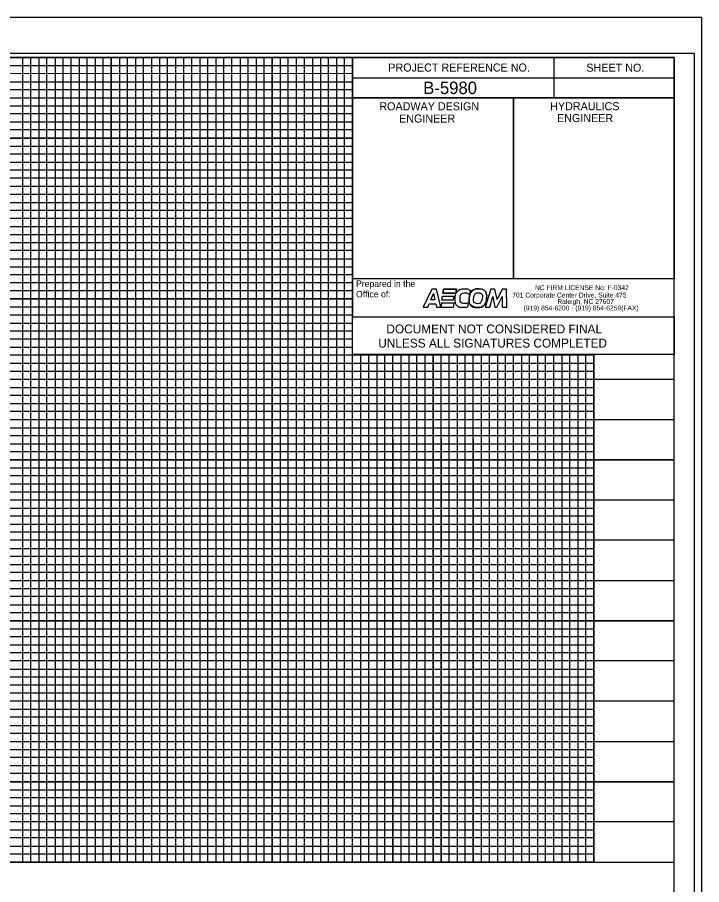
# Model space of a CAD drawing. Extents: x 2356353 to 2358037, y 848519 to 849619.
# Drawn here: x 2357612 to 2358037, y 849080 to 849619 of the extents above; entities that cross this region are included whole.
import ezdxf

# ---------------------------------------------------------------- set-up
doc = ezdxf.new("R2010")
doc.units = 0
for name, color, linetype in [('Default', 7, 'Continuous'), ('Old_Level_49', 7, 'Continuous'), ('Sheet Cutting Line CELL', 7, 'Continuous'), ('Sheet Data Field CELL', 7, 'Continuous'), ('Sheet DOT Grid CELL', 7, 'Continuous'), ('Sheet Layout Profile Border Port 1', 7, 'Continuous'), ('Sheet Plot Border Inside CELL', 7, 'Continuous'), ('Sheet Plot Border Outside CELL', 7, 'Continuous'), ('Sheet Profile CELL', 7, 'Continuous'), ('Sheet Profile Grid Major CELL', 7, 'Continuous'), ('Sheet Profile Grid Middle CELL', 7, 'Continuous'), ('Sheet Profile Grid Minor CELL', 7, 'Continuous'), ('Sheet Sticker Exception Certification CELL', 7, 'Continuous')]:
    doc.layers.add(name, color=color, linetype=linetype)

# ---------------------------------------------------------------- blocks, each defined once
blk = doc.blocks.new('block 2')
at = {"layer": 'Default'}
for p, q in [((0.10137, 0.08733), (0.10174, 0.08975)), ((0.10174, 0.08975), (0.10818, 0.08975)), ((0.10234, 0.09375), (0.10197, 0.09133)), ((0.10197, 0.09133), (0.10929, 0.09133)), ((0.10966, 0.09375), (0.10234, 0.09375)), ((0.10818, 0.08975), (0.10782, 0.08733)), ((0.10929, 0.09133), (0.10966, 0.09375)), ((0.10114, 0.08576), (0.10078, 0.08333)), ((0.10846, 0.08576), (0.10114, 0.08576)), ((0.10782, 0.08733), (0.10137, 0.08733)), ((0.1081, 0.08333), (0.10846, 0.08576)), ((0.10078, 0.08333), (0.1081, 0.08333))]:
    blk.add_line(p, q, dxfattribs=at)
for points in [[(0.10782, 0.08733), (0.10137, 0.08733), (0.10174, 0.08975), (0.10818, 0.08975), (0.10782, 0.08733)], [(0.10929, 0.09133), (0.10197, 0.09133), (0.10234, 0.09375), (0.10966, 0.09375), (0.10929, 0.09133)], [(0.10846, 0.08576), (0.10114, 0.08576), (0.10078, 0.08333), (0.1081, 0.08333), (0.10846, 0.08576)]]:
    blk.add_lwpolyline(points, dxfattribs=at)
blk = doc.blocks.new('block 3')
at = {"layer": 'Default'}
blk.add_open_spline([(0.12275, 0.09393), (0.12554, 0.09373), (0.12726, 0.09146), (0.12695, 0.08843), (0.12663, 0.08531), (0.12411, 0.08298), (0.12127, 0.08318), (0.11848, 0.08338), (0.11676, 0.08565), (0.11707, 0.08868), (0.11739, 0.0918), (0.11991, 0.09413), (0.12275, 0.09393)], degree=3, dxfattribs=at)

msp = doc.modelspace()

# ---------------------------------------------------------------- linework, layer by layer
at = {"layer": 'Default'}
msp.add_lwpolyline([(2357970.19, 849409.89), (2357970.19, 849094.44), (2356570.19, 849094.44), (2356570.19, 849594.44), (2357820.14, 849594.44), (2357820.14, 849433.39), (2357970.19, 849433.39)], dxfattribs=at)
at = {"layer": 'Old_Level_49'}
for p, q in [((2357869.37, 849450.55), (2357864.05, 849439.25)), ((2357868.86, 849443.95), (2357870.5, 849447.87)), ((2357872.43, 849450.55), (2357869.37, 849450.55)), ((2357870.5, 849447.87), (2357870.52, 849447.87)), ((2357870.52, 849447.87), (2357871.36, 849443.95)), ((2357875.04, 849439.25), (2357872.43, 849450.55)), ((2357906.11, 849450.55), (2357902.6, 849439.25)), ((2357908.65, 849450.55), (2357906.11, 849450.55)), ((2357909.97, 849444.18), (2357908.65, 849450.55)), ((2357913.23, 849450.55), (2357909.97, 849444.18)), ((2357915.78, 849450.55), (2357913.23, 849450.55)), ((2357915.99, 849439.25), (2357915.78, 849450.55)), ((2357871.36, 849443.95), (2357868.86, 849443.95)), ((2357905.41, 849439.25), (2357907.32, 849445.87)), ((2357907.32, 849445.87), (2357908.52, 849439.25)), ((2357909.95, 849439.25), (2357913.26, 849445.86)), ((2357913.26, 849445.86), (2357913.22, 849439.25)), ((2357864.05, 849439.25), (2357866.89, 849439.25)), ((2357866.89, 849439.25), (2357867.81, 849441.46)), ((2357867.81, 849441.46), (2357871.88, 849441.46)), ((2357871.88, 849441.46), (2357872.35, 849439.25)), ((2357872.35, 849439.25), (2357875.04, 849439.25)), ((2357902.6, 849439.25), (2357905.41, 849439.25)), ((2357908.52, 849439.25), (2357909.95, 849439.25)), ((2357913.22, 849439.25), (2357915.99, 849439.25))]:
    msp.add_line(p, q, dxfattribs=at)
for points in [[(2357872.35, 849439.25), (2357875.04, 849439.25), (2357872.43, 849450.55), (2357869.37, 849450.55), (2357864.05, 849439.25), (2357866.89, 849439.25), (2357867.81, 849441.46), (2357871.88, 849441.46), (2357872.35, 849439.25)], [(2357868.86, 849443.95), (2357870.5, 849447.87), (2357870.52, 849447.87), (2357871.36, 849443.95), (2357868.86, 849443.95)], [(2357915.99, 849439.25), (2357915.78, 849450.55), (2357913.23, 849450.55), (2357909.97, 849444.18), (2357908.65, 849450.55), (2357906.11, 849450.55), (2357902.6, 849439.25), (2357905.41, 849439.25), (2357907.32, 849445.87), (2357908.52, 849439.25), (2357909.95, 849439.25), (2357913.26, 849445.86), (2357913.22, 849439.25), (2357915.99, 849439.25)]]:
    msp.add_lwpolyline(points, dxfattribs=at)
for points in [[(2357892.13, 849442.15), (2357891.37, 849441.8), (2357890.24, 849441.74), (2357889.68, 849441.74), (2357887.9, 849441.74), (2357886.71, 849442.96), (2357886.77, 849444.78), (2357886.84, 849446.69), (2357888.28, 849448.06), (2357890.25, 849448.06), (2357891.18, 849448.06), (2357892, 849447.76), (2357892.73, 849447.13), (2357892.73, 849447.13), (2357893.27, 849449.84), (2357893.27, 849449.84), (2357892.15, 849450.5), (2357891.21, 849450.77), (2357890.03, 849450.77), (2357886.78, 849450.77), (2357884.09, 849448.06), (2357883.98, 849444.66), (2357883.87, 849441.35), (2357886.02, 849439.03), (2357889.21, 849439.03), (2357889.76, 849439.03), (2357890.96, 849439.09), (2357891.72, 849439.44), (2357891.72, 849439.44), (2357892.13, 849442.15), (2357892.13, 849442.15)], [(2357892.13, 849442.15), (2357891.37, 849441.8), (2357890.24, 849441.74), (2357889.68, 849441.74), (2357887.9, 849441.74), (2357886.71, 849442.96), (2357886.77, 849444.78), (2357886.84, 849446.69), (2357888.28, 849448.06), (2357890.25, 849448.06), (2357891.18, 849448.06), (2357892, 849447.76), (2357892.73, 849447.13), (2357892.73, 849447.13), (2357893.27, 849449.84), (2357893.27, 849449.84), (2357892.15, 849450.5), (2357891.21, 849450.77), (2357890.03, 849450.77), (2357886.78, 849450.77), (2357884.09, 849448.06), (2357883.98, 849444.66), (2357883.87, 849441.35), (2357886.02, 849439.03), (2357889.21, 849439.03), (2357889.76, 849439.03), (2357890.96, 849439.09), (2357891.72, 849439.44), (2357891.72, 849439.44), (2357892.13, 849442.15), (2357892.13, 849442.15)], [(2357896.09, 849439.3), (2357893.78, 849439.99), (2357892.42, 849442.21), (2357892.71, 849445.05), (2357893.06, 849448.44), (2357895.8, 849450.97), (2357898.88, 849450.75)], [(2357900.75, 849444.51), (2357901.16, 849446.42), (2357900.45, 849447.91), (2357899, 849448.2), (2357897.42, 849448.53), (2357895.97, 849447.31), (2357895.54, 849445.29), (2357895.13, 849443.38), (2357895.84, 849441.89), (2357897.28, 849441.6), (2357898.87, 849441.27), (2357900.31, 849442.49), (2357900.75, 849444.51)], [(2357900.75, 849444.51), (2357901.16, 849446.42), (2357900.45, 849447.91), (2357899, 849448.2), (2357897.42, 849448.53), (2357895.97, 849447.31), (2357895.54, 849445.29), (2357895.13, 849443.38), (2357895.84, 849441.89), (2357897.28, 849441.6), (2357898.87, 849441.27), (2357900.31, 849442.49), (2357900.75, 849444.51)], [(2357898.88, 849450.75), (2357901.91, 849450.53), (2357903.78, 849448.07), (2357903.44, 849444.78), (2357903.09, 849441.39), (2357900.35, 849438.87), (2357897.27, 849439.09), (2357896.86, 849439.12), (2357896.46, 849439.19), (2357896.09, 849439.3)]]:
    msp.add_open_spline(points, degree=3, dxfattribs=at)
at = {"layer": 'Sheet Cutting Line CELL'}
msp.add_line((2358037.19, 849619.44), (2356353.19, 849619.44), dxfattribs=at)
at = {"layer": 'Sheet DOT Grid CELL'}
for p, q in [((2357620.19, 849094.44), (2357620.19, 849594.44)), ((2357670.19, 849094.44), (2357670.19, 849594.44)), ((2357720.19, 849094.44), (2357720.19, 849594.44)), ((2357770.19, 849094.44), (2357770.19, 849594.44)), ((2357820.14, 849544.44), (2356520.19, 849544.44)), ((2357820.14, 849494.44), (2356520.19, 849494.44)), ((2357820.19, 849094.44), (2357820.19, 849456.89)), ((2357820.19, 849444.44), (2356520.19, 849444.44)), ((2357870.19, 849094.44), (2357870.19, 849409.89)), ((2357920.19, 849094.44), (2357920.19, 849409.89)), ((2357970.19, 849094.44), (2357970.19, 849409.89)), ((2358020.19, 849394.44), (2356520.19, 849394.44)), ((2358020.19, 849344.44), (2356520.19, 849344.44)), ((2358020.19, 849294.44), (2356520.19, 849294.44)), ((2358020.19, 849244.44), (2356520.19, 849244.44)), ((2358020.19, 849194.44), (2356520.19, 849194.44)), ((2358020.19, 849144.44), (2356520.19, 849144.44))]:
    msp.add_line(p, q, dxfattribs=at)
at = {"layer": 'Sheet Layout Profile Border Port 1'}
msp.add_lwpolyline([(2356570.19, 849433.39), (2356570.19, 849094.44), (2357970.19, 849094.44), (2357970.19, 849409.89)], dxfattribs=at)
at = {"layer": 'Sheet Plot Border Inside CELL'}
msp.add_lwpolyline([(2356366.19, 848541.89), (2358032.69, 848541.89), (2358032.69, 849596.99), (2356366.19, 849596.99)], close=True, dxfattribs=at)
at = {"layer": 'Sheet Plot Border Outside CELL'}
msp.add_lwpolyline([(2356353.19, 848519.44), (2358037.19, 848519.44), (2358037.19, 849619.44), (2356353.19, 849619.44)], close=True, dxfattribs=at)
at = {"layer": 'Sheet Profile CELL'}
for p, q in [((2357945.19, 849594.39), (2357945.19, 849569.39)), ((2357820.14, 849581.89), (2358020.19, 849581.89)), ((2357920.19, 849569.39), (2357920.19, 849456.94)), ((2357820.14, 849456.89), (2357820.14, 849433.39)), ((2356520.19, 849094.44), (2358020.19, 849094.44))]:
    msp.add_line(p, q, dxfattribs=at)
for points in [[(2358020.19, 849594.44), (2356520.19, 849594.44), (2356520.19, 848544.44), (2358020.19, 848544.44)], [(2357820.14, 849594.44), (2358020.19, 849594.44), (2358020.19, 849569.39), (2357820.14, 849569.39)], [(2357820.14, 849569.39), (2357920.19, 849569.39), (2357920.19, 849456.89), (2357820.14, 849456.89)], [(2357920.19, 849569.39), (2358020.19, 849569.39), (2358020.19, 849456.89), (2357920.19, 849456.89)]]:
    msp.add_lwpolyline(points, close=True, dxfattribs=at)
at = {"layer": 'Sheet Profile Grid Major CELL'}
for points in [[(2357570.19, 849094.44), (2357620.19, 849094.44), (2357620.19, 849594.44), (2357670.19, 849594.44), (2357670.19, 849094.44), (2357720.19, 849094.44), (2357720.19, 849594.44), (2357770.19, 849594.44), (2357770.19, 849094.44), (2357820.19, 849094.44), (2357820.19, 849594.44), (2357846.49, 849594.44)], [(2356520.19, 849544.44), (2357820.19, 849544.44)], [(2357820.19, 849494.44), (2356520.19, 849494.44), (2356520.19, 849444.44), (2357820.19, 849444.44)], [(2357970.19, 849409.89), (2357970.19, 849094.44), (2358020.19, 849094.44), (2358020.19, 849444.44)], [(2357870.19, 849409.89), (2357870.19, 849094.44), (2357920.19, 849094.44), (2357920.19, 849094.44), (2357920.19, 849409.89)], [(2358020.19, 849394.44), (2356520.19, 849394.44), (2356520.19, 849344.44), (2358020.19, 849344.44)], [(2358020.19, 849294.44), (2356520.19, 849294.44), (2356520.19, 849244.44), (2358020.19, 849244.44)], [(2358020.19, 849194.44), (2356520.19, 849194.44), (2356520.19, 849194.44), (2356520.19, 849144.44), (2358020.19, 849144.44)]]:
    msp.add_lwpolyline(points, dxfattribs=at)
at = {"layer": 'Sheet Profile Grid Middle CELL'}
msp.add_line((2356520.19, 849569.44), (2357820.14, 849569.44), dxfattribs=at)
for points in [[(2357595.19, 849094.44), (2357645.19, 849094.44), (2357645.19, 849594.44), (2357695.19, 849594.44), (2357695.19, 849094.44), (2357745.19, 849094.44), (2357745.19, 849594.44), (2357795.19, 849594.44), (2357795.19, 849094.44), (2357845.19, 849094.44), (2357845.19, 849409.89)], [(2357820.19, 849519.44), (2356520.19, 849519.44), (2356520.19, 849469.44), (2357820.19, 849469.44)], [(2357820.19, 849419.44), (2356520.19, 849419.44), (2356520.19, 849369.44), (2357845.19, 849369.44)], [(2357845.19, 849357.24), (2357845.19, 849094.44), (2357895.19, 849094.44), (2357895.19, 849409.89)], [(2357895.19, 849357.24), (2357895.19, 849094.44), (2357945.19, 849094.44), (2357945.19, 849409.89)], [(2357845.19, 849369.44), (2358020.19, 849369.44)], [(2358020.19, 849319.44), (2356520.19, 849319.44), (2356520.19, 849269.44), (2358020.19, 849269.44)], [(2358020.19, 849219.44), (2356520.19, 849219.44), (2356520.19, 849169.44), (2358020.19, 849169.44)], [(2358020.19, 849119.44), (2356520.19, 849119.44)]]:
    msp.add_lwpolyline(points, dxfattribs=at)
at = {"layer": 'Sheet Profile Grid Minor CELL'}
for p, q in [((2356570.19, 849589.44), (2357820.19, 849589.44)), ((2357820.19, 849584.44), (2356570.19, 849584.09)), ((2356570.19, 849579.44), (2357820.19, 849579.44)), ((2357820.14, 849459.44), (2356570.19, 849459.44)), ((2357820.19, 849454.44), (2356570.19, 849454.44)), ((2357820.19, 849449.44), (2356570.19, 849449.44)), ((2356570.19, 849439.44), (2357820.19, 849439.44)), ((2357820.19, 849434.44), (2356570.19, 849434.44)), ((2356570.19, 849429.44), (2357820.19, 849429.44)), ((2357970.19, 849409.44), (2356570.19, 849409.44)), ((2356570.19, 849404.44), (2357970.19, 849404.44)), ((2357970.19, 849384.44), (2356570.19, 849384.44)), ((2356570.19, 849379.44), (2357970.19, 849379.44)), ((2357970.19, 849359.44), (2356570.19, 849359.44)), ((2356570.19, 849354.44), (2357970.19, 849354.44)), ((2357970.19, 849349.44), (2356570.19, 849349.44)), ((2356570.19, 849339.44), (2357970.19, 849339.44)), ((2357970.19, 849334.44), (2356570.19, 849334.44)), ((2356570.19, 849329.44), (2357970.19, 849329.44)), ((2357970.19, 849324.44), (2356570.19, 849324.44)), ((2356570.19, 849314.44), (2357970.19, 849314.44)), ((2357970.19, 849309.44), (2356570.19, 849309.44)), ((2356570.19, 849304.44), (2357970.19, 849304.44)), ((2357970.19, 849299.44), (2356570.19, 849299.44)), ((2356570.19, 849289.44), (2357970.19, 849289.44)), ((2357970.19, 849284.44), (2356570.19, 849284.44)), ((2356570.19, 849279.44), (2357970.19, 849279.44)), ((2357970.19, 849274.44), (2356570.19, 849274.44)), ((2356570.19, 849264.44), (2357970.19, 849264.44)), ((2357970.19, 849259.44), (2356570.19, 849259.44)), ((2356570.19, 849254.44), (2357970.19, 849254.44)), ((2357970.19, 849249.44), (2356570.19, 849249.44)), ((2356570.19, 849239.44), (2357970.19, 849239.44)), ((2357970.19, 849234.44), (2356570.19, 849234.44)), ((2356570.19, 849229.44), (2357970.19, 849229.44)), ((2357970.19, 849224.44), (2356570.19, 849224.44)), ((2356570.19, 849214.44), (2357970.19, 849214.44)), ((2357970.19, 849209.44), (2356570.19, 849209.44)), ((2357970.19, 849204.44), (2356570.19, 849204.44)), ((2357970.19, 849199.44), (2356570.19, 849199.44)), ((2356570.19, 849189.44), (2357970.19, 849189.44)), ((2357970.19, 849184.44), (2356570.19, 849184.44)), ((2356570.19, 849179.44), (2357970.19, 849179.44)), ((2357970.19, 849174.44), (2356570.19, 849174.44)), ((2356570.19, 849164.44), (2357970.19, 849164.44)), ((2357970.19, 849159.44), (2356570.19, 849159.44)), ((2356570.19, 849154.44), (2357970.19, 849154.44)), ((2357970.19, 849149.44), (2356570.19, 849149.44)), ((2356570.19, 849139.44), (2357970.19, 849139.44)), ((2357970.19, 849134.44), (2356570.19, 849134.44)), ((2356570.19, 849129.44), (2357970.19, 849129.44)), ((2357970.19, 849124.44), (2356570.19, 849124.44)), ((2356570.19, 849114.44), (2357970.19, 849114.44)), ((2357970.19, 849109.44), (2356570.19, 849109.44)), ((2356570.19, 849104.44), (2357970.19, 849104.44))]:
    msp.add_line(p, q, dxfattribs=at)
for points in [[(2357610.19, 849094.44), (2357615.19, 849094.44), (2357615.19, 849594.44), (2357625.19, 849594.44), (2357625.19, 849094.44), (2357630.19, 849094.44), (2357630.19, 849594.44), (2357635.19, 849594.44), (2357635.19, 849094.44), (2357640.19, 849094.44), (2357640.19, 849594.44), (2357650.19, 849594.44), (2357650.19, 849094.44), (2357655.19, 849094.44), (2357655.19, 849594.44), (2357660.19, 849594.44), (2357660.19, 849094.44), (2357665.19, 849094.44), (2357665.19, 849594.44), (2357675.19, 849594.44), (2357675.19, 849094.44), (2357680.19, 849094.44), (2357680.19, 849594.44), (2357685.19, 849594.44), (2357685.19, 849094.44), (2357690.19, 849094.44), (2357690.19, 849594.44), (2357700.19, 849594.44), (2357700.19, 849094.44), (2357705.19, 849094.44), (2357705.19, 849594.44), (2357710.19, 849594.44), (2357710.19, 849094.44)], [(2357710.19, 849094.44), (2357715.19, 849094.44), (2357715.19, 849594.44), (2357725.19, 849594.44), (2357725.19, 849094.44), (2357730.19, 849094.44), (2357730.19, 849594.44), (2357735.19, 849594.44), (2357735.19, 849094.44), (2357740.19, 849094.44), (2357740.19, 849594.44), (2357750.19, 849594.44), (2357750.19, 849094.44), (2357755.19, 849094.44), (2357755.19, 849594.44), (2357760.19, 849594.44), (2357760.19, 849094.44), (2357765.19, 849094.44), (2357765.19, 849594.44), (2357775.19, 849594.44), (2357775.19, 849094.44), (2357780.19, 849094.44), (2357780.19, 849594.44), (2357785.19, 849594.44), (2357785.19, 849094.44), (2357790.19, 849094.44), (2357790.19, 849594.44), (2357800.19, 849594.44), (2357800.19, 849094.44), (2357805.19, 849094.44), (2357805.19, 849594.44), (2357810.19, 849594.44), (2357810.19, 849094.44), (2357815.19, 849094.44), (2357815.19, 849594.44), (2357825.19, 849594.44)], [(2357820.19, 849574.44), (2356570.19, 849574.44), (2356570.19, 849564.44), (2357820.19, 849564.44)], [(2357820.14, 849559.44), (2356570.19, 849559.44), (2356570.19, 849554.44), (2357820.19, 849554.44)], [(2357820.19, 849549.44), (2356570.19, 849549.44), (2356570.19, 849539.44), (2357820.19, 849539.44)], [(2357820.19, 849534.44), (2356570.19, 849534.44), (2356570.19, 849529.44), (2357820.19, 849529.44)], [(2357820.19, 849524.44), (2356570.19, 849524.44), (2356570.19, 849514.44), (2357820.19, 849514.44)], [(2357820.19, 849509.44), (2356570.19, 849509.44), (2356570.19, 849504.44), (2357820.19, 849504.44)], [(2357820.19, 849499.44), (2356570.19, 849499.44), (2356570.19, 849489.44), (2357820.19, 849489.44)], [(2357820.19, 849484.34), (2356570.29, 849484.34), (2356570.29, 849479.44), (2357820.19, 849479.44)], [(2357820.19, 849474.44), (2356570.19, 849474.44), (2356570.19, 849464.44), (2357820.19, 849464.44)], [(2357820.19, 849424.44), (2356570.19, 849424.44), (2356570.19, 849414.44), (2357820.19, 849414.44)], [(2357825.19, 849409.89), (2357825.19, 849094.44), (2357830.19, 849094.44), (2357830.19, 849409.89)], [(2357835.19, 849409.89), (2357835.19, 849094.44), (2357840.19, 849094.44), (2357840.19, 849409.89)], [(2357850.19, 849409.89), (2357850.19, 849094.44), (2357850.19, 849094.44), (2357855.19, 849094.44), (2357860.19, 849094.44), (2357860.19, 849409.89)], [(2357855.19, 849409.89), (2357855.19, 849094.44)], [(2357865.17, 849409.89), (2357865.09, 849094.49), (2357870.09, 849094.49), (2357875.19, 849094.44), (2357875.19, 849409.89)], [(2357875.19, 849357.24), (2357875.19, 849094.44), (2357880.19, 849094.44), (2357880.19, 849409.89)], [(2357885.19, 849409.89), (2357885.19, 849094.44), (2357890.19, 849094.44), (2357890.19, 849409.89)], [(2357900.19, 849409.89), (2357900.19, 849094.44), (2357905.19, 849094.44), (2357905.19, 849409.89)], [(2357910.19, 849409.89), (2357910.19, 849094.44), (2357915.19, 849094.44), (2357915.19, 849409.89)], [(2357925.19, 849409.89), (2357925.19, 849094.44), (2357930.19, 849094.44), (2357930.19, 849409.89)], [(2357935.19, 849409.89), (2357935.19, 849094.44), (2357940.19, 849094.44), (2357940.19, 849409.89)], [(2357950.19, 849409.89), (2357950.19, 849094.44), (2357955.19, 849094.44), (2357955.19, 849409.89)], [(2357960.19, 849409.89), (2357960.19, 849094.44), (2357965.19, 849094.44), (2357965.19, 849409.89)], [(2357970.19, 849399.44), (2356570.19, 849399.44), (2356570.19, 849389.44), (2357970.19, 849389.44)], [(2357970.19, 849374.44), (2356570.19, 849374.44), (2356570.19, 849364.44), (2357970.19, 849364.44)], [(2357970.19, 849099.44), (2356570.19, 849099.44)]]:
    msp.add_lwpolyline(points, dxfattribs=at)
at = {"layer": 'Sheet Sticker Exception Certification CELL'}
msp.add_lwpolyline([(2357820.14, 849433.39), (2358020.17, 849433.39), (2358020.17, 849409.89), (2357820.14, 849409.89)], close=True, dxfattribs=at)

# ---------------------------------------------------------------- block references
at = {"layer": 'Old_Level_49', "xscale": 1084.8432715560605, "yscale": 1084.8432715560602, "rotation": -0.003580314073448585}
for name in ['block 2', 'block 3']:
    msp.add_blockref(name, (2357765.71, 849348.86), dxfattribs=at)

# ---------------------------------------------------------------- texts
at = {"layer": 'Old_Level_49'}
for s, height, p in [('Prepared in the ', 4.0179, (2357822.32, 849451.93)), ('Office of:', 4.018, (2357822.32, 849445.41)), ('701 Corporate Center Drive, Suite 475', 3.0135, (2357919.44, 849445.32)), ('NC FIRM LICENSE No: F-0342', 3.0135, (2357933.59, 849449.95)), ('Raleigh, NC 27607', 3.0135, (2357947.46, 849441.32)), ('(919) 854-6200 - (919) 854-6259(FAX)', 3.0135, (2357926.51, 849437.32))]:
    msp.add_text(s, height=height, rotation=359.9964, dxfattribs=at).set_placement(p)
at = {"layer": 'Sheet Data Field CELL'}
msp.add_text('B-5980', height=7.75, dxfattribs=at).set_placement((2357864.09, 849571.75))
at = {"layer": 'Sheet Profile CELL'}
for s, height, p in [('PROJECT REFERENCE NO.', 5.0001, (2357842.35, 849585.75)), ('SHEET NO.', 5, (2357965.5, 849585.65)), ('ROADWAY DESIGN', 5.0001, (2357836.8, 849561.65)), ('HYDRAULICS', 5, (2357943, 849561.7)), ('ENGINEER', 5, (2357849.05, 849554.05)), ('ENGINEER', 5, (2357947.25, 849554.35))]:
    msp.add_text(s, height=height, dxfattribs=at).set_placement(p)
at = {"layer": 'Sheet Sticker Exception Certification CELL'}
for s, p in [('DOCUMENT NOT CONSIDERED FINAL', (2357841.21, 849423.04)), ('UNLESS ALL SIGNATURES COMPLETED', (2357836.14, 849414.24))]:
    msp.add_text(s, height=5.5, dxfattribs=at).set_placement(p)

doc.saveas('drawing.dxf')
